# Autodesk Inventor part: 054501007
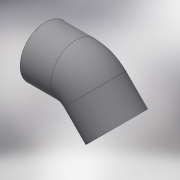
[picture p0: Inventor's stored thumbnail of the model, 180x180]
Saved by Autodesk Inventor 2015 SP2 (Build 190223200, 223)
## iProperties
Created: 2017-10
Part Number: 054501007
Material: Generic
Description: PLASSON THREADED 45° ELBOW HF 3/4"
Document SubType Name: Modeling
Designer: KIM
Mass: 15.1023 g
Surface Area: 88.7639 cm^2
Volume: 15.1023 cm^3
Density: 1 g/cm^3
Appearance: Default
Author: KIM
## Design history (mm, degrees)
derived "054501.ipt"
feature "Solid1::054501.ipt"
tag "TaggingFeature1"
body "Solid1"
other parameters: "d7" = 0.24117, "d9" = 31, "d13" = 135 deg, "d18" = 6, "d19" = 45 deg, "d20" = 24.117, "d21" = 18, "d22" = 0, "d28" = 24, "d29" = 24.117, "d30" = 18, "d31" = 0, "d32" = 21.7053, "d33" = 45 deg, "E_" = 31, "lt_" = 18, "Z_" = 6, "G_" = 24.117
